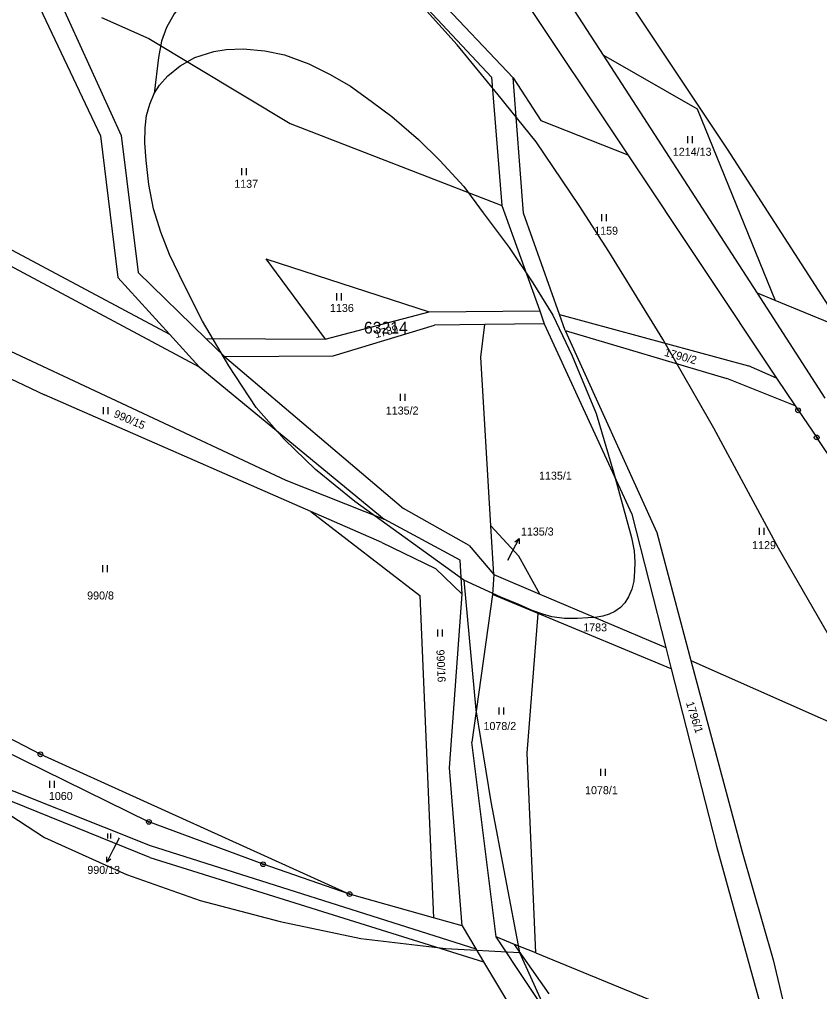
# Model space of a CAD drawing. Extents: x -546762 to -540209, y -1046851 to -1035694.
# Drawn here: x -543476.6 to -543306.6, y -1041824.4 to -1041617.8 of the extents above; entities that cross this region are included whole.
import ezdxf

# ---------------------------------------------------------------- set-up
doc = ezdxf.new("R2010")
doc.units = 0
for name, color, linetype in [('Vrstva 1', 7, 'Continuous'), ('Vrstva 16', 7, 'Continuous'), ('Vrstva 18', 7, 'Continuous'), ('Vrstva 24', 7, 'Continuous'), ('Vrstva 25', 7, 'Continuous'), ('Vrstva 52', 7, 'Continuous'), ('Vrstva 53', 7, 'Continuous'), ('Vrstva 6', 7, 'Continuous')]:
    doc.layers.add(name, color=color, linetype=linetype)

msp = doc.modelspace()

# ---------------------------------------------------------------- linework, layer by layer
at = {"layer": 'Vrstva 1'}
for p, q in [((-543414.67, -1041722.37), (-543471.29, -1041697.61)), ((-543414.67, -1041722.37), (-543391.53, -1041740.27)), ((-543399.62, -1041728.95), (-543414.67, -1041722.37)), ((-543370.5, -1041731.89), (-543376.46, -1041725.46)), ((-543366.05, -1041739.95), (-543370.5, -1041731.89)), ((-543375.84, -1041735.8), (-543366.05, -1041739.95)), ((-543391.53, -1041740.27), (-543388.62, -1041808.71)), ((-543366.4, -1041744.07), (-543376.11, -1041740.04)), ((-543366.05, -1041739.95), (-543339.29, -1041751.3)), ((-543368.72, -1041773.72), (-543366.4, -1041744.07)), ((-543338.13, -1041755.82), (-543366.4, -1041744.07)), ((-543366.93, -1041816.2), (-543368.72, -1041773.72)), ((-543388.62, -1041808.71), (-543406.46, -1041803.7)), ((-543382.58, -1041810.41), (-543388.62, -1041808.71)), ((-543366.93, -1041816.2), (-543371.4, -1041814.37)), ((-543366.93, -1041816.2), (-543321.94, -1041834.61))]:
    msp.add_line(p, q, dxfattribs=at)
for points in [[(-543352.54, -1041625.45), (-543386.07, -1041573.62)], [(-543393.66, -1041577.13), (-543347.39, -1041646.58)], [(-543474.24, -1041611.09), (-543459.39, -1041642.58)], [(-543468.12, -1041613.49), (-543454.95, -1041642.46)], [(-543388.33, -1041612.61), (-543371.71, -1041630.24)], [(-543390.96, -1041614.47), (-543376.34, -1041630.09)], [(-543459.13, -1041617.45), (-543449.1, -1041621.88)], [(-543449.1, -1041621.88), (-543419.1, -1041639.94)], [(-543319.84, -1041675.99), (-543352.54, -1041625.45)], [(-543376.34, -1041630.09), (-543374.09, -1041657.34)], [(-543371.71, -1041630.24), (-543365.81, -1041639.3)], [(-543369.51, -1041659.01), (-543371.71, -1041630.24)], [(-543419.1, -1041639.94), (-543374.09, -1041657.34)], [(-543365.81, -1041639.3), (-543347.39, -1041646.58)], [(-543459.39, -1041642.58), (-543455.68, -1041672.66)], [(-543454.95, -1041642.46), (-543451.33, -1041671.57)], [(-543347.39, -1041646.58), (-543315.76, -1041694.05)], [(-543374.09, -1041657.34), (-543366.08, -1041679.76)], [(-543361.9, -1041680.54), (-543369.51, -1041659.01)], [(-543424.26, -1041668.68), (-543411.65, -1041685.78)], [(-543424.26, -1041668.68), (-543389.56, -1041679.99)], [(-543451.33, -1041671.57), (-543436.97, -1041685.6)], [(-543455.68, -1041672.66), (-543444.74, -1041684.68)], [(-543517.81, -1041675.5), (-543471.29, -1041697.61)], [(-543305.42, -1041698.29), (-543319.84, -1041675.99)], [(-543411.65, -1041685.78), (-543389.56, -1041679.99)], [(-543389.56, -1041679.99), (-543366.08, -1041679.76)], [(-543366.08, -1041679.76), (-543365.11, -1041682.48)], [(-543365.11, -1041682.48), (-543377.74, -1041682.64)], [(-543365.11, -1041682.48), (-543346.53, -1041722.97)], [(-543360.7, -1041683.93), (-543361.9, -1041680.54)], [(-543361.9, -1041680.54), (-543321.74, -1041691.44)], [(-543409.98, -1041689.3), (-543388.41, -1041682.77)], [(-543377.74, -1041682.64), (-543388.41, -1041682.77)], [(-543378.59, -1041689.62), (-543377.74, -1041682.64)], [(-543360.7, -1041683.93), (-543326.31, -1041694.11)], [(-543360.7, -1041683.93), (-543341.22, -1041726.85)], [(-543444.74, -1041684.68), (-543438.41, -1041691.63)], [(-543436.97, -1041685.6), (-543411.65, -1041685.78)], [(-543436.97, -1041685.6), (-543433.06, -1041689.42)], [(-543433.06, -1041689.42), (-543409.98, -1041689.3)], [(-543433.06, -1041689.42), (-543394.99, -1041721.72)], [(-543376.46, -1041725.46), (-543378.59, -1041689.62)], [(-543438.41, -1041691.63), (-543399.15, -1041724)], [(-543315.76, -1041694.05), (-543321.74, -1041691.44)], [(-543311.82, -1041699.97), (-543326.31, -1041694.11)], [(-543315.76, -1041694.05), (-543311.82, -1041699.97)], [(-543311.82, -1041699.97), (-543311.2, -1041700.89)], [(-543311.2, -1041700.89), (-543307.25, -1041706.66)], [(-543250.12, -1041791.8), (-543307.25, -1041706.66)], [(-543381.08, -1041729.6), (-543394.99, -1041721.72)], [(-543346.53, -1041722.97), (-543339.29, -1041751.3)], [(-543383, -1041732.74), (-543399.15, -1041724)], [(-543375.84, -1041735.8), (-543376.46, -1041725.46)], [(-543341.22, -1041726.85), (-543333.96, -1041754.04)], [(-543399.62, -1041728.95), (-543388.21, -1041734.5)], [(-543381.08, -1041729.6), (-543375.84, -1041735.8)], [(-543382.54, -1041739.97), (-543383, -1041732.74)], [(-543388.21, -1041734.5), (-543382.54, -1041739.97)], [(-543375.84, -1041735.8), (-543376.11, -1041740.04)], [(-543385.26, -1041776.85), (-543382.54, -1041739.97)], [(-543376.11, -1041740.04), (-543380.51, -1041771.43)], [(-543339.29, -1041751.3), (-543338.13, -1041755.82)], [(-543333.96, -1041754.04), (-543323.11, -1041794.69)], [(-543333.96, -1041754.04), (-543278.41, -1041778.7)], [(-543338.13, -1041755.82), (-543328.5, -1041793.51)], [(-543490.01, -1041764.71), (-543472.12, -1041773.99)], [(-543489.3, -1041768.58), (-543449.09, -1041788.35)], [(-543375.34, -1041812.76), (-543380.51, -1041771.43)], [(-543472.12, -1041773.99), (-543406.46, -1041803.7)], [(-543382.58, -1041810.41), (-543385.26, -1041776.85)], [(-543424.83, -1041797.35), (-543449.09, -1041788.35)], [(-543328.5, -1041793.51), (-543318.45, -1041829.9)], [(-543323.11, -1041794.69), (-543316.46, -1041817.63)], [(-543406.46, -1041803.7), (-543424.83, -1041797.35)], [(-543382.58, -1041810.41), (-543379.66, -1041815.3)], [(-543371.4, -1041814.37), (-543375.34, -1041812.76)], [(-543362.55, -1041831.96), (-543375.34, -1041812.76)], [(-543379.66, -1041815.3), (-543378.01, -1041818.06)], [(-543378.01, -1041818.06), (-543365.29, -1041839.33)], [(-543316.46, -1041817.63), (-543313.5, -1041830.21)]]:
    msp.add_lwpolyline(points, dxfattribs=at)
at = {"layer": 'Vrstva 16'}
for p, q in [((-543371.83, -1041730.81), (-543370.42, -1041728.16)), ((-543456.67, -1041794.24), (-543458.04, -1041796.91))]:
    msp.add_line(p, q, dxfattribs=at)
for points in [[(-543371.33, -1041728.81), (-543370.42, -1041728.16), (-543370.45, -1041729.28)], [(-543372.83, -1041732.71), (-543371.83, -1041730.81)], [(-543455.41, -1041791.79), (-543456.67, -1041794.24)], [(-543457.14, -1041796.25), (-543458.04, -1041796.91), (-543458.03, -1041795.79)]]:
    msp.add_lwpolyline(points, dxfattribs=at)
at = {"layer": 'Vrstva 24'}
for centre, radius in [((-543311.2, -1041700.89), 0.5), ((-543311.2, -1041700.89), 0.1), ((-543307.25, -1041706.66), 0.5), ((-543307.25, -1041706.66), 0.1), ((-543472.12, -1041773.99), 0.5), ((-543472.12, -1041773.99), 0.1), ((-543449.09, -1041788.35), 0.5), ((-543449.09, -1041788.35), 0.1), ((-543424.83, -1041797.35), 0.5), ((-543424.83, -1041797.35), 0.1), ((-543406.46, -1041803.7), 0.5), ((-543406.46, -1041803.7), 0.1)]:
    msp.add_circle(centre, radius, dxfattribs=at)
at = {"layer": 'Vrstva 25'}
for p, q in [((-543334.6, -1041644.1), (-543334.6, -1041642.6)), ((-543333.6, -1041644.1), (-543333.6, -1041642.6)), ((-543429.38, -1041650.9), (-543429.38, -1041649.4)), ((-543428.38, -1041650.9), (-543428.38, -1041649.4)), ((-543352.91, -1041660.69), (-543352.91, -1041659.19)), ((-543351.91, -1041660.69), (-543351.91, -1041659.19)), ((-543409.18, -1041677.53), (-543409.18, -1041676.03)), ((-543408.18, -1041677.53), (-543408.18, -1041676.03)), ((-543395.67, -1041698.89), (-543395.67, -1041697.39)), ((-543394.67, -1041698.89), (-543394.67, -1041697.39)), ((-543458.74, -1041701.7), (-543458.74, -1041700.2)), ((-543457.74, -1041701.7), (-543457.74, -1041700.2)), ((-543319.37, -1041727.37), (-543319.37, -1041725.87)), ((-543318.37, -1041727.37), (-543318.37, -1041725.87)), ((-543458.87, -1041735.29), (-543458.87, -1041733.79)), ((-543457.87, -1041735.29), (-543457.87, -1041733.79)), ((-543387.75, -1041748.94), (-543387.75, -1041747.44)), ((-543386.75, -1041748.94), (-543386.75, -1041747.44)), ((-543374.68, -1041765.51), (-543374.68, -1041764.01)), ((-543373.68, -1041765.51), (-543373.68, -1041764.01)), ((-543353.09, -1041778.58), (-543353.09, -1041777.08)), ((-543352.09, -1041778.58), (-543352.09, -1041777.08)), ((-543470.16, -1041781.09), (-543470.16, -1041779.59)), ((-543469.16, -1041781.09), (-543469.16, -1041779.59)), ((-543457.81, -1041791.85), (-543457.81, -1041790.84)), ((-543457.14, -1041791.85), (-543457.14, -1041790.84))]:
    msp.add_line(p, q, dxfattribs=at)
at = {"layer": 'Vrstva 52'}
for points in [[(-543392.03, -1041564.88), (-543389.35, -1041566.27), (-543386.34, -1041568.52), (-543379.06, -1041575.45), (-543371.08, -1041584.75), (-543348.51, -1041611.96), (-543326.23, -1041645.4), (-543279.72, -1041717.53)], [(-543395.27, -1041610.2), (-543399.84, -1041608.95), (-543404.96, -1041607.78), (-543411.53, -1041606.67), (-543419.15, -1041606.32), (-543424.89, -1041606.6), (-543429.18, -1041607.22), (-543432.85, -1041608.12), (-543436.24, -1041609.65), (-543439.29, -1041611.58), (-543441.36, -1041613.73), (-543443.71, -1041616.64), (-543445.37, -1041619.55), (-543446.41, -1041622.46), (-543447.04, -1041625.92), (-543447.98, -1041633.54)], [(-543223.2, -1041845.14), (-543243.97, -1041823.94), (-543264.74, -1041802.94), (-543284.03, -1041778.77), (-543300.77, -1041755.44), (-543315.39, -1041730.21), (-543329.12, -1041704.67), (-543339.93, -1041685.8), (-543351.37, -1041667.14), (-543357.73, -1041657.38), (-543366.84, -1041643.81), (-543374.9, -1041633.85), (-543383.59, -1041623.24), (-543395.27, -1041610.2)], [(-543447.98, -1041633.54), (-543446.81, -1041631.81), (-543445.08, -1041629.81), (-543442.45, -1041627.66), (-543439.33, -1041625.93), (-543435.32, -1041624.61), (-543432.69, -1041624.23), (-543429.09, -1041624.08), (-543424.47, -1041624.47)], [(-543424.47, -1041624.47), (-543420.31, -1041625.38), (-543415.13, -1041627.28), (-543410.62, -1041629.5), (-543406.27, -1041631.99), (-543401.85, -1041635.19), (-543397.5, -1041638.48), (-543391.8, -1041643.34), (-543387.26, -1041647.79), (-543382.21, -1041653.33), (-543378.06, -1041658.93), (-543372.59, -1041666.27), (-543367.54, -1041673.82), (-543363.27, -1041680.7), (-543359.15, -1041689.3), (-543354.07, -1041701.54), (-543350.31, -1041714.26), (-543346.56, -1041727.95), (-543346.03, -1041730.73), (-543345.88, -1041733.19), (-543345.92, -1041735.09), (-543346.07, -1041737.18), (-543346.51, -1041738.88), (-543347.22, -1041740.51), (-543348.01, -1041741.81), (-543348.92, -1041742.8), (-543350.15, -1041743.67), (-543351.33, -1041744.23), (-543352.68, -1041744.66), (-543354.3, -1041744.9), (-543355.88, -1041745.02), (-543358.02, -1041745.14), (-543360.82, -1041745.14), (-543363.51, -1041744.78), (-543365.41, -1041744.19), (-543367.7, -1041743.4), (-543370.51, -1041742.17), (-543374.31, -1041740.59), (-543382.21, -1041736.98)], [(-543604.74, -1041627.67), (-543598.75, -1041638.61), (-543590.45, -1041655.43), (-543579.55, -1041677.14), (-543570.64, -1041692.62), (-543559.84, -1041709.16), (-543548.39, -1041723.16), (-543537.14, -1041735.5), (-543520.61, -1041752.25), (-543503.44, -1041767.52), (-543485.85, -1041782.15), (-543471.23, -1041791.69), (-543453.85, -1041799.54), (-543438.17, -1041805.05), (-543421.21, -1041809.5), (-543404.04, -1041813.11), (-543386.03, -1041815.23), (-543370.35, -1041816.08)], [(-543382.21, -1041736.98), (-543405.35, -1041720.28), (-543413.71, -1041713.47), (-543420.37, -1041707.04), (-543426.31, -1041700.26), (-543432.12, -1041691.41), (-543437.69, -1041681.96), (-543441.69, -1041674.09), (-543444.71, -1041667.78), (-543446.53, -1041663.06), (-543448.11, -1041658.09), (-543449.07, -1041652.88), (-543449.68, -1041647.79), (-543449.92, -1041644.07), (-543449.85, -1041640.88), (-543449.58, -1041638.25), (-543448.88, -1041635.83), (-543447.98, -1041633.54)], [(-543382.21, -1041736.98), (-543379.67, -1041764.55), (-543376.49, -1041784.06), (-543370.35, -1041816.08)], [(-543370.35, -1041816.08), (-543363.99, -1041830.17)]]:
    msp.add_lwpolyline(points, dxfattribs=at)
at = {"layer": 'Vrstva 6'}
for points in [[(-543352.54, -1041625.45), (-543332.6, -1041636.81)], [(-543332.6, -1041636.81), (-543316.09, -1041677.54)], [(-543490.78, -1041660.13), (-543444.74, -1041684.68)], [(-543493.9, -1041661.99), (-543438.41, -1041691.63)], [(-543517.99, -1041669.81), (-543419.99, -1041715.71)], [(-543316.09, -1041677.54), (-543319.84, -1041675.99)], [(-543298.18, -1041684.9), (-543316.09, -1041677.54)], [(-543419.99, -1041715.71), (-543399.15, -1041724)], [(-543487.58, -1041777.92), (-543448.8, -1041793.4)], [(-543448.9, -1041795.89), (-543488.61, -1041779.85)], [(-543448.8, -1041793.4), (-543379.66, -1041815.3)], [(-543448.9, -1041795.89), (-543378.01, -1041818.06)], [(-543364.07, -1041824.9), (-543371.4, -1041814.37)]]:
    msp.add_lwpolyline(points, dxfattribs=at)

# ---------------------------------------------------------------- texts
at = {"layer": 'Vrstva 16'}
for s, p in [('1135/3', (-543370.07, -1041727.5)), ('990/13', (-543462.16, -1041799.4))]:
    msp.add_text(s, height=1.7, dxfattribs=at).set_placement(p)
at = {"layer": 'Vrstva 18'}
for s, height, p in [('1214/13', 1.7, (-543337.81, -1041646.8)), ('1137', 1.7, (-543430.96, -1041653.61)), ('1159', 1.7, (-543354.5, -1041663.58)), ('1136', 1.7, (-543410.62, -1041679.99)), ('1135/2', 1.7, (-543398.77, -1041701.79)), ('1135/1', 1.7, (-543366.22, -1041715.63)), ('1129', 1.7, (-543320.96, -1041730.38)), ('1135/3', 0.1, (-543372.83, -1041732.71)), ('990/8', 1.7, (-543462.2, -1041741.09)), ('1783', 1.7, (-543356.84, -1041747.87)), ('1078/2', 1.7, (-543378.02, -1041768.83)), ('1078/1', 1.7, (-543356.45, -1041782.46)), ('1060', 1.7, (-543470.33, -1041783.69)), ('990/13', 0.1, (-543455.63, -1041791.79))]:
    msp.add_text(s, height=height, dxfattribs=at).set_placement(p)
for s, rotation, p in [('1789', 14.2207, (-543400.9, -1041685.58)), ('1790/2', 344.5157, (-543339.72, -1041689.28)), ('990/15', 336.8286, (-543456.71, -1041702.26)), ('990/16', 272.4347, (-543388.03, -1041751.77)), ('1796/1', 287.7152, (-543335.04, -1041763.06))]:
    msp.add_text(s, height=1.7, rotation=rotation, dxfattribs=at).set_placement(p)
at = {"layer": 'Vrstva 53'}
msp.add_text('63214', height=2.5, dxfattribs=at).set_placement((-543403.41, -1041684.58))

doc.saveas('drawing.dxf')
